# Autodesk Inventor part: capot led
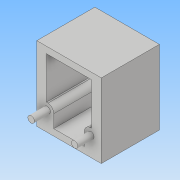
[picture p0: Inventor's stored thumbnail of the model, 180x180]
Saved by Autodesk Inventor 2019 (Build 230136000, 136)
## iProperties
Created: 2024-09
Part Number: capot led
Material: Générique
Document SubType Name: Modeling
Designer: admin
Density: 1 g/cm^3
Appearance: Par défaut
Author: admin
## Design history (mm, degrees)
sketch "Esquisse1"
  geometry: L1 (-10, 11.5)-(10, 11.5); L2 (10, 11.5)-(10, -11.5); L3 (10, -11.5)-(-10, -11.5); L4 (-10, -11.5)-(-10, 11.5); L5 (-7, 0)-(7, 0); L6 (7, 0)-(7, -1.5); L7 (7, -1.5)-(-7, -1.5); L8 (-7, -1.5)-(-7, 0); 1 further point
  constraints: 16 end point, 4 parallel, 2 horizontal, 2 perpendicular
  dimensions: "d0" = 20 distance of L2.end L3.end; "d1" = 23 distance of L3.end L1.start; "d2" = 10 distance from line of point (0, 0) L4 (= 0.5 x d0); "d3" = 11.5 distance from line of L3 point (0, 0) (= 0.5 x d1); "d4" = 10 distance between parallel lines of L3 L7; "d5" = 1.5 distance of L7.end L5.start; "d6" = 3 distance between parallel lines of L4 L8; "d7" = 3 distance between parallel lines of L2 L6
extrude "Extrusion1" new body sketch "Esquisse1" distance "d8" = 3; taper "d9" = 0 deg
sketch "Esquisse2"
  geometry: L1 (7, -1.5)-(-7, -1.5) reference; L2 (4.75, -5.5)-(4.75, -9.5); L3 (4.75, -9.5)-(-4.75, -9.5); L4 (-4.75, -9.5)-(-4.75, -5.5); L5 (-10, -11.5)-(10, -11.5) reference; L6 (7, -3.516)-(7, 9.5); L7 (7, 9.5)-(-7, 9.5); L8 (-7, 9.5)-(-7, -3.516); L9 (10, 11.5)-(-10, 11.5) reference; L10 (-7, -3.516)-(-6.5, -3.516); L11 (6.5, -3.516)-(7, -3.516); L12 (7, 0)-(7, -1.5) reference; L13 (7, -1.5)-(-7, -1.5) reference; L14 (-7, -1.5)-(-7, 0) reference; L15 (-7, 0)-(7, 0) reference; L16 (10, 11.5)-(-10, 11.5) reference; L17 (-10, 11.5)-(-10, -11.5) reference; L18 (-10, -11.5)-(10, -11.5) reference; L19 (10, -11.5)-(10, 11.5) reference; A1 r 2 centre (-6.75, -5.5) between (-4.75, -5.5) and (-7, -3.516); A2 r 2 centre (6.75, -5.5) between (7, -3.516) and (4.75, -5.5); 1 further point
  constraints: 16 end point, 6 point on circle, 4 parallel, 2 centre point, 2 horizontal, 2 perpendicular
  dimensions: "d10" = 4 distance from line of L1 A1.centre; "d11" = 4 diameter of A1; "d12" = 4 diameter of A2; "d13" = 4 distance from line of L1 A2.centre; "d14" = 13.5 distance of A1.centre A2.centre; "d15" = 6.75 horizontal distance of point (0, 0) A1.centre (= 0.5 x d14); "d16" = 2 distance between parallel lines of L5 L3; "d17" = 2 distance between parallel lines of L9 L7
extrude "Extrusion2" join sketch "Esquisse2" distance "d18" = 15; taper "d19" = 0 deg
sketch "Esquisse3"
  geometry: L1 (-6.5, -3.516)-(-7, -3.516) reference; L2 (-7, -3.516)-(-7, 9.5) reference; L3 (-7, 9.5)-(7, 9.5) reference; L4 (7, 9.5)-(7, -3.516) reference; L5 (7, -3.516)-(6.5, -3.516) reference; L6 (4.75, -5.5)-(4.75, -9.5) reference; L7 (4.75, -9.5)-(-4.75, -9.5) reference; L8 (-4.75, -9.5)-(-4.75, -5.5) reference; L9 (10, 11.5)-(-10, 11.5) reference; L10 (-10, 11.5)-(-10, -11.5) reference; L11 (-10, -11.5)-(10, -11.5) reference; L12 (10, -11.5)-(10, 11.5) reference; C1 r 1 at (-6.75, -5.5); C2 r 1 at (6.75, -5.5); A1 r 2 centre (-6.75, -5.5) between (-4.75, -5.5) and (-6.5, -3.516) reference; A2 r 2 centre (6.75, -5.5) between (6.5, -3.516) and (4.75, -5.5) reference; 1 further point
  constraints: 2 centre point, 2 coincident
  dimensions: "d20" = 2 diameter of C1; "d21" = 2 diameter of C2
extrude "Extrusion3" join sketch "Esquisse3" distance "d22" = 5; taper "d23" = 0 deg
node "Solide1"
node "Boucle projetée1"
node "Boucle projetée2"
